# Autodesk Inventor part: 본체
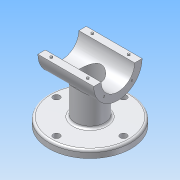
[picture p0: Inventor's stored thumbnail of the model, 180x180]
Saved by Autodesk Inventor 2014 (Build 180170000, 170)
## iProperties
Created: 2015-12
Part Number: 본체
Material: 알루미늄 6061
Document SubType Name: Modeling
Designer: mduedu
Density: 2.71 g/cm^3
Mass: 472.289 g
Surface Area: 460.062 cm^2
Volume: 174.276 cm^3
Appearance: 알루미늄 - 평지
Author: mduedu
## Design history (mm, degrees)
sketch "스케치1"
  geometry: C1 r 55 at (0, 0); 1 further point
  constraints: 1 centre point, 1 coincident
  dimensions: "d124" = 110 diameter of C1
extrude "돌출1" new body sketch "스케치1" distance "d3" = 10; taper "d4" = 0 deg
sketch "스케치2"
  geometry: C1 r 32.5 at (80, 0); 1 further point
  constraints: 1 centre point, 1 horizontal alignment
  dimensions: "d5" = 65 diameter of C1; "d125" = 80 distance of C1.centre point (0, 0)
extrude "돌출2" join sketch "스케치2" stored distance "d7" = 75; taper "d8" = 0 deg
sketch "스케치3"
  geometry: C1 r 20 at (0, 0); 1 further point
  constraints: 1 centre point, 1 coincident
  dimensions: "d154" = 40 diameter of C1
extrude "돌출3" new body sketch "스케치3" stored distance "d12" = 75; taper "d13" = 0 deg
feature "결합1"
  node "솔리드2"
fillet "모깎기13" dims "d155" = 3
fillet "모깎기7" dims "d41" = 3
hole "구멍2" diameter "d44" = 45; stored, may be unused: countersink angle "d48" = 90 deg, drill point angle "d50" = 118 deg; dims "d42" = 10, "d43" = 10, "d45" = 6, "d46" = 4, "d47" = 2, "d49" = 8
sketch "스케치7" dims "d52" = 26.5
  geometry: L1 (0, 0)-(32.5, 0); L2 (0, 0)-(22.981, 22.981); A1 r 32.5 centre (0, 0) between (32.5, 0) and (22.981, 22.981) reference; 3 further points
  constraints: 4 end point, 2 point on circle, 1 coincident, 1 horizontal, 1 point on line, 3 other
  dimensions: "d51" = 45 deg angle of L2 L1
hole "구멍3" sketch "스케치7" at (18.738, 18.738) diameter "d54" = 2.459; stored, may be unused: countersink angle "d58" = 90 deg, drill point angle "d60" = 118 deg; dims "d55" = 8, "d56" = 4, "d57" = 2, "d59" = 10
sketch "스케치9"
  geometry: L1 (-75, 82.5)-(75, 82.5); L2 (75, 82.5)-(75, 0); L3 (75, 0)-(-75, 0); L4 (-75, 0)-(-75, 82.5); C1 r 32.5 at (0, 0) reference; 2 further points
  constraints: 8 end point, 2 parallel, 1 coincident, 1 horizontal, 1 midpoint, 1 perpendicular
  dimensions: "d71" = 50 distance edge to line of C1 L1; "d116" = 150 distance between parallel lines of L2 L4
extrude "돌출5" cut sketch "스케치9" stored distance "d73" = 0; taper "d74" = 0 deg
node "작업 평면1"
sketch "스케치10"
  geometry: C1 r 15 at (0, 0); 1 further point
  constraints: 1 centre point, 1 coincident
  dimensions: "d156" = 30 diameter of C1
extrude "돌출6" cut sketch "스케치10" stored distance "d78" = 50; taper "d79" = 0 deg
sketch "스케치11"
  geometry: 2 further points
  constraints: 1 coincident
hole "구멍4" sketch "스케치11" at (0, 0) diameter "d81" = 12; stored, may be unused: countersink angle "d85" = 90 deg, drill point angle "d87" = 118 deg; dims "d82" = 8, "d83" = 30, "d84" = 10, "d86" = 10
sketch "스케치12"
  geometry: C1 r 10 at (0, 0); 1 further point
  constraints: 1 centre point, 1 coincident
  dimensions: "d88" = 20 diameter of C1
extrude "돌출7" cut sketch "스케치12" distance "d89" = 10; taper "d90" = 0 deg
chamfer "모따기1" distance "d91" = 1; stored, may be unused: second distance "d92" = 2, angle "d93" = 45 deg
sketch "스케치15"
  geometry: L1 (-75, 55)-(-75, 65) reference; L2 (0, 65)-(0, 55) reference; L3 (-75, 60)-(0, 60); C1 r 1.5 at (-62, 60); 1 further point
  constraints: 2 end point, 2 midpoint, 1 centre point, 1 point on line
  dimensions: "d117" = 3 diameter of C1; "d118" = 13 distance from line of C1.centre L1
extrude "돌출8" join sketch "스케치15" distance "d119" = 1.8; taper "d120" = 0 deg
chamfer "모따기2" distance "d121" = 0.5; stored, may be unused: second distance "d122" = 2, angle "d123" = 45 deg
sketch "스케치18" dims "d141" = 90
  geometry: C1 r 52 at (0, 0) reference; 2 further points
  constraints: 2 vertical alignment, 1 coincident, 2 other
hole "구멍8" sketch "스케치18" at (0, 45) diameter "d142" = 9; stored, may be unused: countersink angle "d146" = 90 deg, drill point angle "d148" = 118 deg; dims "d143" = 6, "d144" = 4, "d145" = 2, "d147" = 8
node "솔리드1"
pattern_circular "원형 패턴1" dims angle "d62" = 360 deg
mirror "대칭3"
mirror "대칭5"
mirror "대칭6"
pattern_circular "원형 패턴2" dims angle "d150" = 360 deg
